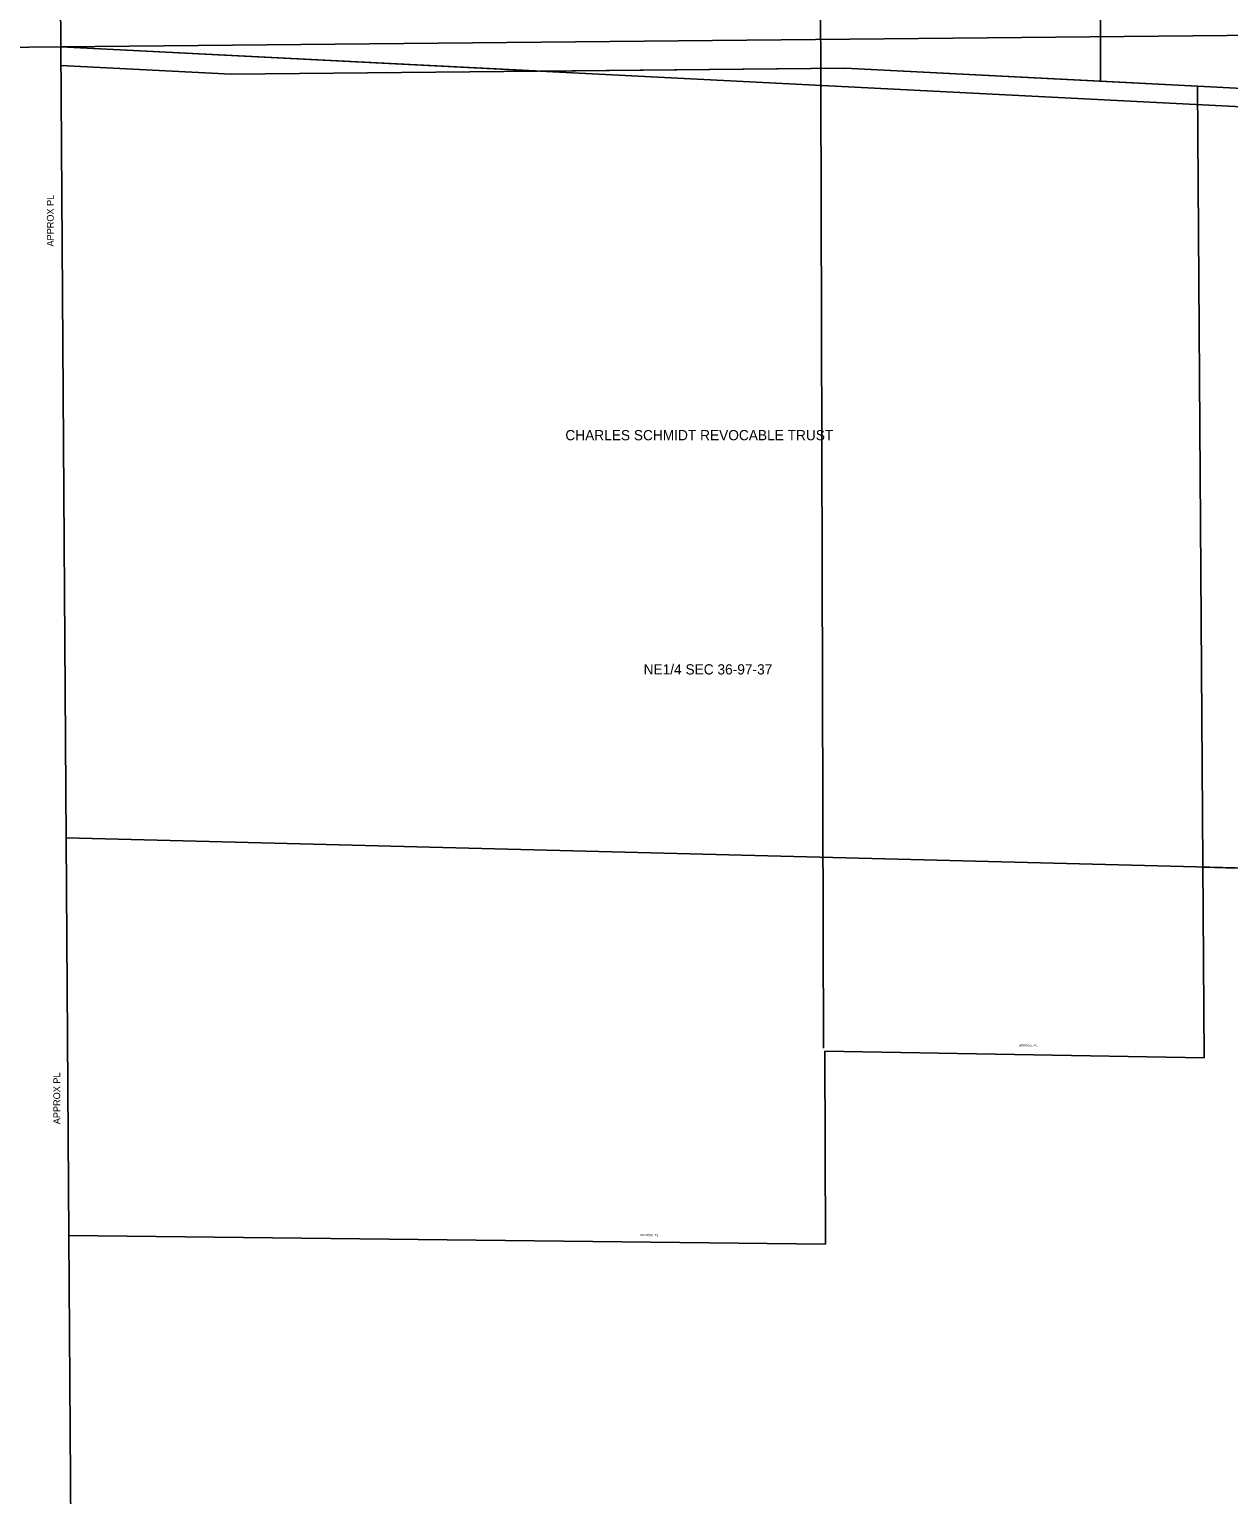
# Model space of a CAD drawing. Extents: x 11521219 to 11528920, y 9587418 to 9599499.
# Drawn here: x 11523817 to 11525924, y 9591637 to 9594212 of the extents above; entities that cross this region are included whole.
import ezdxf

# ---------------------------------------------------------------- set-up
doc = ezdxf.new("R2010")
doc.units = 0
for name, color, linetype in [('Alignment', 7, 'Continuous'), ('DisROW Existing', 7, 'Continuous'), ('DisROW Property Lines', 7, 'Continuous'), ('Section Lines', 7, 'Continuous'), ('Text', 7, 'Continuous')]:
    doc.layers.add(name, color=color, linetype=linetype)

msp = doc.modelspace()

# ---------------------------------------------------------------- linework, layer by layer
at = {"layer": 'Alignment'}
msp.add_line((11523871.9, 9594181.4), (11526572.4, 9594207.2), dxfattribs=at)
at = {"layer": 'DisROW Existing'}
for p, q in [((11524171.3, 9594133.1), (11523872.1, 9594148.3)), ((11525249.6, 9594143.6), (11524171.3, 9594133.1)), ((11525249.6, 9594143.6), (11525869.3, 9594112.3)), ((11525869.3, 9594112.3), (11526113.9, 9594099.8))]:
    msp.add_line(p, q, dxfattribs=at)
at = {"layer": 'DisROW Property Lines'}
for p, q in [((11525699.1, 9594120.9), (11525699.2, 9594615.3)), ((11522545.5, 9594167.1), (11523871.9, 9594181.4)), ((11524717.7, 9594138.4), (11523871.9, 9594181.4)), ((11523871.9, 9594181.4), (11523886.2, 9592092.8)), ((11525249.6, 9594143.6), (11524717.7, 9594138.4)), ((11525699.1, 9594120.9), (11525249.6, 9594143.6)), ((11525869.3, 9594112.3), (11525699.1, 9594120.9)), ((11525869.3, 9594112.3), (11525880.9, 9592405)), ((11525869.3, 9594112.3), (11526113.9, 9594099.8)), ((11526544.3, 9592723.2), (11525878.7, 9592739.8)), ((11525215.8, 9592077.5), (11525214.5, 9592416.9)), ((11525214.5, 9592416.9), (11525880.9, 9592405)), ((11523886.2, 9592092.8), (11525215.8, 9592077.5))]:
    msp.add_line(p, q, dxfattribs=at)
at = {"layer": 'Section Lines'}
for p, q in [((11523871.9, 9594181.4), (11523858.4, 9596749.7)), ((11525207.2, 9594113.6), (11525200.6, 9596718.9)), ((11521219.2, 9594152.9), (11523871.9, 9594181.4)), ((11526542.5, 9594045.8), (11523871.9, 9594181.4)), ((11525207.2, 9594113.6), (11525212.3, 9592421.9)), ((11523881.5, 9592791.3), (11526544.3, 9592723.2)), ((11523886.2, 9592092.8), (11523891, 9591396.7))]:
    msp.add_line(p, q, dxfattribs=at)

# ---------------------------------------------------------------- texts
at = {"layer": 'Text'}
for s, height, rotation, p in [('APPROX PL', 12, 90, (11523859.6, 9593830.4)), ('APPROX. PL', 3.9, 359, (11525555.8, 9592424.8)), ('APPROX PL', 12, 90, (11523871, 9592288.3)), ('APPROX. PL', 3.9, 359, (11524890, 9592091.9))]:
    msp.add_text(s, height=height, rotation=rotation, dxfattribs=at).set_placement(p)
for s, p in [('CHARLES SCHMIDT REVOCABLE TRUST', (11524758.6, 9593490)), ('NE1/4 SEC 36-97-37', (11524896.1, 9593078.5))]:
    msp.add_text(s, height=18, dxfattribs=at).set_placement(p)

doc.saveas('drawing.dxf')
